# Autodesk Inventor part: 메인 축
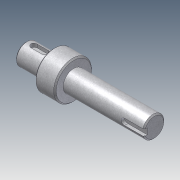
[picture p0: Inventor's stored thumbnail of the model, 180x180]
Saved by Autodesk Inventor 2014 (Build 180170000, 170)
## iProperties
Company: 한국ATC센터
Created: 2014-10
Part Number: 메인 축
Document SubType Name: Modeling
Designer: KYOUNG IL JANG
Density: 1 g/cm^3
Mass: 29.2926 g
Surface Area: 74.3518 cm^2
Volume: 29.2926 cm^3
Material: Generic
Appearance: Metal-Steel (Stainless, Brushed)
Author: KYOUNG IL JANG
Revision Number: 1
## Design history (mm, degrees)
sketch "스케치1"
  geometry: L1 (10.497, -57.5)-(112.497, -57.5); L2 (10.497, -66)-(32.497, -66); L3 (32.497, -72.5)-(46.5, -72.5); L4 (46.5, -66)-(112.497, -66); L5 (112.497, -66)-(112.497, -57.5); L6 (10.497, -66)-(10.497, -57.5); L7 (46.5, -69.749)-(46.5, -45.251) reference; L8 (46.5, -72.5)-(46.5, -66); L9 (32.497, -72.5)-(32.497, -66); L10 (32.497, -35)-(32.497, -80) reference; 3 further points
  constraints: 16 end point, 3 point on line, 2 parallel, 2 perpendicular, 1 collinear, 1 horizontal, 1 midpoint
  dimensions: "d0" = 17 diameter of L4 L1; "d1" = 30 diameter of L3 L1; "d2" = 22 distance of L2.start L2.end; "d3" = 65.99692 distance of L4.start L4.end (derived); "d5" = 17 diameter of L2 L1; "d19" = 80 distance between parallel lines of L5 L9
revolve "회전1" sketch "스케치1" stored, may be unused: angle "d4" = 90 deg
chamfer "모따기1" distance "d6" = 1; stored, may be unused: second distance "d7" = 2, angle "d8" = 45 deg
node "작업 평면1"
sketch "스케치2"
  geometry: L1 (-11, -7.5)-(-11, 7.5) reference; L2 (-4.5, 2.5)-(4.5, 2.5); L3 (4.5, -2.5)-(-4.5, -2.5); A1 r 2.5 centre (4.5, 0) between (4.5, -2.5) and (4.5, 2.5); A2 r 2.5 centre (-4.5, 0) between (-4.5, 2.5) and (-4.5, -2.5); 2 further points
  constraints: 4 end point, 4 point on circle, 4 tangent, 2 centre point, 1 horizontal alignment, 1 midpoint, 1 parallel, 1 perpendicular
  dimensions: "d9" = 5 distance between parallel lines of L3 L2; "d10" = 14 dimension on A1 A2; "d11" = 4 distance edge to line of A2 L1
extrude "돌출1" cut sketch "스케치2" distance "d12" = 3; taper "d13" = 0 deg
node "작업 평면2"
sketch "스케치3"
  geometry: L1 (32.998, 7.5)-(32.998, -7.5) reference; L2 (32.998, 2.5)-(17.498, 2.5); L3 (17.498, -2.5)-(32.998, -2.5); A1 r 2.5 centre (17.498, 0) between (17.498, 2.5) and (17.498, -2.5); 2 further points
  constraints: 4 end point, 2 perpendicular, 2 point on circle, 2 point on line, 2 tangent, 1 centre point, 1 horizontal alignment, 1 midpoint
  dimensions: "d14" = 5 distance between parallel lines of L3 L2; "d15" = 18 dimension on A1 L1
extrude "돌출2" cut sketch "스케치3" distance "d16" = 3; taper "d17" = 0 deg
node "솔리드1"
node "참조4"
node "참조5"
